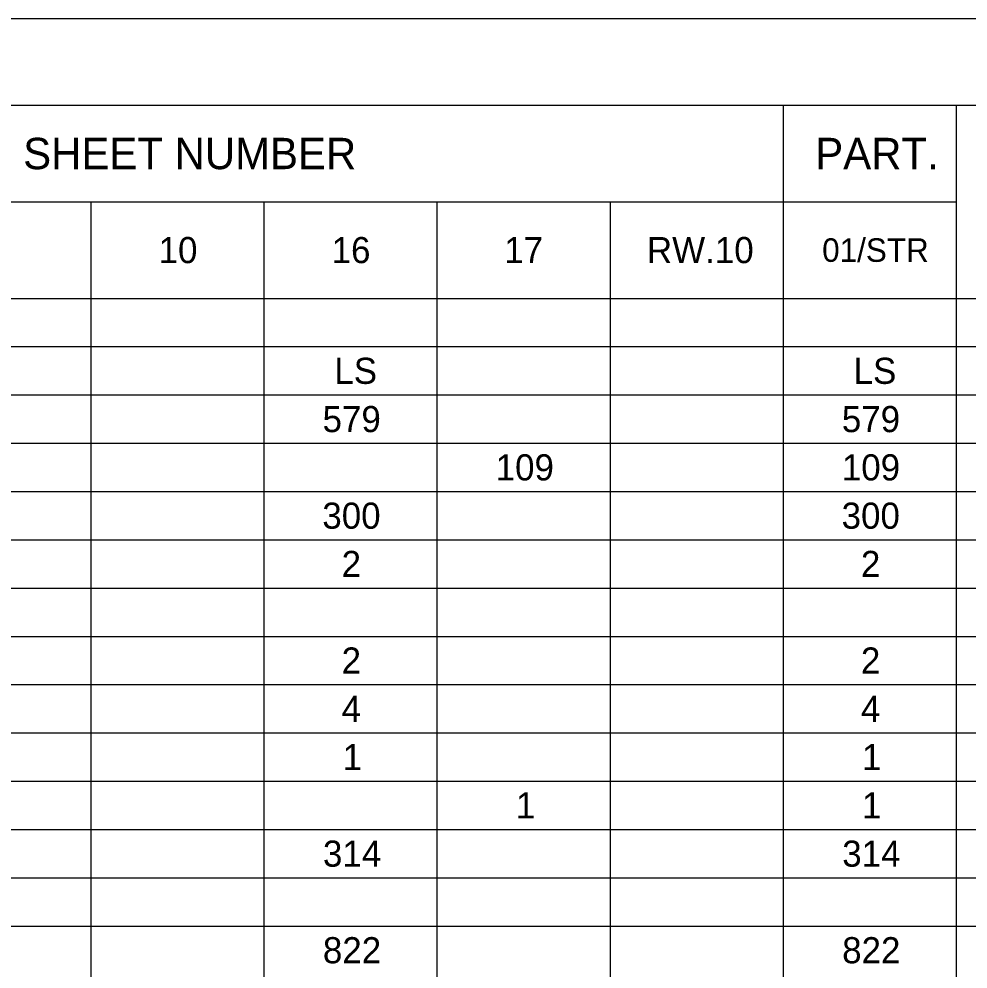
# Model space of a CAD drawing. Extents: x 0 to 34, y 0 to 22.
# Drawn here: x 4.1 to 9.6, y 16.49 to 22 of the extents above; entities that cross this region are included whole.
import ezdxf

# ---------------------------------------------------------------- set-up
doc = ezdxf.new("R2010")
doc.units = 0
for name, color, linetype in [('Default', 7, 'Continuous'), ('SH_Border', 7, 'Continuous'), ('SH_Cut_Line', 7, 'Continuous')]:
    doc.layers.add(name, color=color, linetype=linetype)

msp = doc.modelspace()

# ---------------------------------------------------------------- linework, layer by layer
at = {"layer": 'Default'}
for p, q in [((1.5, 21.5), (32, 21.5)), ((8.5283, 21.5), (8.5283, 0.5)), ((9.5324, 21.5), (9.5324, 0.5)), ((1.5, 20.94), (9.5324, 20.94)), ((4.5121, 20.94), (4.5121, 0.5)), ((5.5162, 20.94), (5.5162, 0.5)), ((6.5202, 20.94), (6.5202, 0.5)), ((7.5243, 20.94), (7.5243, 0.5)), ((1.5, 20.38), (32, 20.38)), ((1.5, 20.1), (32, 20.1)), ((1.5, 19.82), (32, 19.82)), ((1.5, 19.54), (32, 19.54)), ((1.5, 19.26), (32, 19.26)), ((1.5, 18.98), (32, 18.98)), ((1.5, 18.7), (32, 18.7)), ((1.5, 18.42), (32, 18.42)), ((1.5, 18.14), (32, 18.14)), ((1.5, 17.86), (32, 17.86)), ((1.5, 17.58), (32, 17.58)), ((1.5, 17.3), (32, 17.3)), ((1.5, 17.02), (32, 17.02)), ((1.5, 16.74), (32, 16.74))]:
    msp.add_line(p, q, dxfattribs=at)
at = {"layer": 'SH_Border'}
msp.add_lwpolyline([(1.5, 21.5), (33.5, 21.5), (33.5, 0.5), (1.5, 0.5)], close=True, dxfattribs=at)
at = {"layer": 'SH_Cut_Line'}
msp.add_lwpolyline([(0, 0), (34, 0), (34, 22), (0, 22)], close=True, dxfattribs=at)

# ---------------------------------------------------------------- texts
at = {"layer": 'Default'}
for s, height, p in [('SHEET NUMBER', 0.181835, (4.1201, 21.1291)), ('PART.', 0.18184, (8.7146, 21.1291)), ('10', 0.15153, (4.9056, 20.5842)), ('16', 0.15153, (5.9091, 20.5842)), ('17', 0.15153, (6.9104, 20.5842)), ('RW.10', 0.15153, (7.7382, 20.5842)), ('01/STR', 0.13638, (8.7547, 20.5918)), ('LS', 0.15153, (5.9249, 19.8842)), ('LS', 0.15153, (8.937, 19.8842)), ('579', 0.15153, (5.8567, 19.6042)), ('579', 0.15153, (8.8688, 19.6042)), ('109', 0.15153, (6.8607, 19.3242)), ('109', 0.15153, (8.8688, 19.3242)), ('300', 0.15153, (5.8553, 19.0442)), ('300', 0.15153, (8.8675, 19.0442)), ('2', 0.1515, (5.9673, 18.7642)), ('2', 0.1515, (8.9795, 18.7642)), ('2', 0.1515, (5.9673, 18.2042)), ('2', 0.1515, (8.9795, 18.2042)), ('4', 0.1515, (5.9677, 17.9242)), ('4', 0.1515, (8.9799, 17.9242)), ('1', 0.1515, (5.9736, 17.6442)), ('1', 0.1515, (8.9858, 17.6442)), ('1', 0.1515, (6.9777, 17.3642)), ('1', 0.1515, (8.9858, 17.3642)), ('314', 0.15153, (5.859, 17.0842)), ('314', 0.15153, (8.8711, 17.0842)), ('822', 0.15153, (5.8586, 16.5242)), ('822', 0.15153, (8.8707, 16.5242))]:
    msp.add_text(s, height=height, dxfattribs=at).set_placement(p)

doc.saveas('drawing.dxf')
